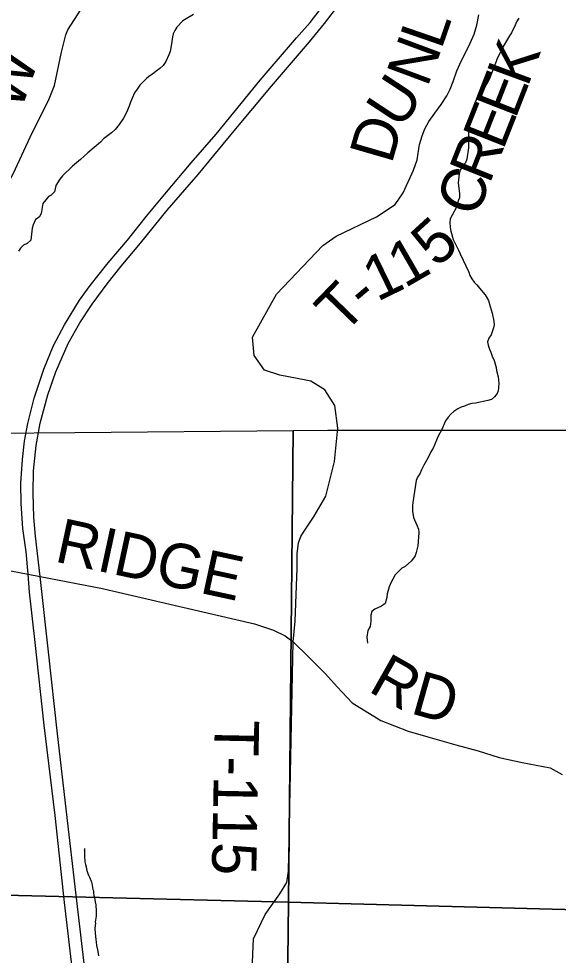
# Model space of a CAD drawing. Extents: x -14196 to 143, y -6096 to 28.
# Drawn here: x 60.879 to 61.569, y 20.751 to 21.949 of the extents above; entities that cross this region are included whole.
import ezdxf

# ---------------------------------------------------------------- set-up
doc = ezdxf.new("R2010")
doc.units = 0
for name, color, linetype in [('GM_X_Corporation', 7, 'Continuous'), ('GM_X_County_Road', 7, 'Continuous'), ('GM_X_County_Road_Text', 7, 'Continuous'), ('GM_X_Interstate_Route', 7, 'Continuous'), ('GM_X_Minor_River', 7, 'Continuous'), ('GM_X_Township_Road', 7, 'Continuous'), ('GM_X_Township_Road_Text', 7, 'Continuous')]:
    doc.layers.add(name, color=color, linetype=linetype)

msp = doc.modelspace()

# ---------------------------------------------------------------- linework, layer by layer
at = {"layer": 'GM_X_Corporation'}
for points in [[(60.9504, 21.4197), (61.23, 21.4222), (61.2237, 20.8189), (60.2211, 20.8437), (60.2221, 21.4121), (60.3073, 21.4131), (60.6364, 21.4168)], [(61.9287, 21.423), (62.2585, 21.4234), (62.2418, 20.9787), (62.2362, 20.7922), (61.2237, 20.8189), (61.23, 21.4222), (61.2736, 21.4223), (61.6017, 21.4227)], [(61.2237, 20.8189), (61.2122, 19.8148), (60.2036, 19.8271), (60.2211, 20.8437)], [(62.2362, 20.7922), (62.2333, 20.6565), (62.2314, 20.3211), (62.2297, 20.027), (62.2277, 19.7879), (61.2122, 19.8148), (61.2237, 20.8189)]]:
    msp.add_lwpolyline(points, close=True, dxfattribs=at)
at = {"layer": 'GM_X_County_Road'}
for points in [[(60.7945, 21.2541), (60.8181, 21.2522), (60.8595, 21.2442), (60.8908, 21.2382), (60.9059, 21.2353), (60.9859, 21.2201), (61.0005, 21.2167)], [(61.0005, 21.2167), (61.1804, 21.175), (61.2048, 21.1669), (61.2196, 21.1595), (61.2299, 21.1519), (61.2496, 21.1326), (61.2712, 21.1111), (61.2863, 21.0942), (61.3053, 21.074), (61.3422, 21.0512), (61.3768, 21.0377), (61.402, 21.0305), (61.4382, 21.0203), (61.4667, 21.0125), (61.4934, 21.0039), (61.5231, 20.9978), (61.5589, 20.9906), (61.5742, 20.9824)]]:
    msp.add_lwpolyline(points, dxfattribs=at)
at = {"layer": 'GM_X_Interstate_Route'}
for points in [[(60.9494, 20.7135), (60.9374, 20.8188), (60.9251, 20.9297), (60.9111, 21.0453), (60.8996, 21.1509), (60.8924, 21.2152), (60.8908, 21.2382), (60.8881, 21.267), (60.884, 21.2968), (60.8817, 21.3286), (60.8815, 21.3549), (60.8835, 21.3851), (60.8858, 21.4083), (60.8904, 21.4309), (60.8985, 21.4634), (60.9108, 21.5006), (60.9233, 21.5309), (60.9374, 21.5572), (60.9564, 21.5885), (60.9702, 21.6074), (60.9932, 21.6365), (61.0177, 21.6654), (61.0421, 21.6959), (61.0657, 21.7243), (61.0991, 21.7641), (61.1311, 21.801), (61.1541, 21.8288), (61.1876, 21.8699), (61.234, 21.9239), (61.2515, 21.9438), (61.2704, 21.9678)], [(60.9644, 20.7226), (60.9522, 20.828), (60.9397, 20.9346), (60.928, 21.0383), (60.917, 21.1353), (60.9059, 21.2353), (60.8999, 21.2871), (60.8979, 21.3107), (60.8969, 21.3419), (60.8977, 21.3704), (60.901, 21.4029), (60.9061, 21.4316), (60.916, 21.4676), (60.9259, 21.4972), (60.942, 21.5331), (60.9569, 21.5597), (60.9726, 21.5834), (60.992, 21.6097), (61.0098, 21.6323), (61.0344, 21.6614), (61.0686, 21.7036), (61.1081, 21.7494), (61.1545, 21.8051), (61.202, 21.8621), (61.2507, 21.9191), (61.27, 21.9423), (61.2882, 21.9665)]]:
    msp.add_lwpolyline(points, dxfattribs=at)
at = {"layer": 'GM_X_Minor_River'}
for points in [[(61.1024, 21.9539), (61.093, 21.9485), (61.0888, 21.9458), (61.0809, 21.9377), (61.0783, 21.9335), (61.0764, 21.9293), (61.0753, 21.9255), (61.0743, 21.9164), (61.0725, 21.9065), (61.0706, 21.9023), (61.0669, 21.8939), (61.0635, 21.8889)], [(61.5185, 21.9491), (61.5155, 21.9445), (61.514, 21.9403), (61.5092, 21.9304), (61.5066, 21.9265), (61.5043, 21.9223), (61.4987, 21.9132), (61.4961, 21.9074), (61.4909, 21.8975), (61.4898, 21.8937), (61.4879, 21.8895), (61.4805, 21.8708), (61.4749, 21.8601), (61.4719, 21.8563), (61.4696, 21.8521), (61.4659, 21.8475), (61.4629, 21.8421), (61.4614, 21.8376), (61.4592, 21.8338), (61.4559, 21.8219), (61.4548, 21.8166), (61.4542, 21.8044), (61.4544, 21.7835), (61.4522, 21.7691), (61.4504, 21.7641), (61.4466, 21.7599), (61.4436, 21.7549), (61.4422, 21.7504), (61.4411, 21.7386), (61.4428, 21.7245), (61.4425, 21.7196), (61.441, 21.7158), (61.4403, 21.712), (61.4388, 21.7078), (61.4332, 21.6975), (61.4309, 21.6925), (61.4302, 21.6883), (61.4307, 21.6815), (61.4315, 21.6769), (61.4346, 21.6663), (61.4416, 21.6527), (61.4436, 21.6478), (61.4545, 21.6243), (61.4561, 21.6201), (61.4584, 21.616), (61.4615, 21.6118), (61.4649, 21.6081), (61.4684, 21.6039), (61.4757, 21.5956), (61.48, 21.5881), (61.482, 21.5805), (61.4847, 21.5722), (61.4867, 21.5619), (61.4872, 21.557), (61.4864, 21.5532), (61.4831, 21.5444), (61.4801, 21.5402), (61.4786, 21.5356), (61.4794, 21.5311), (61.481, 21.5261), (61.483, 21.5224), (61.4845, 21.5171), (61.4869, 21.5114), (61.4896, 21.5027), (61.49, 21.4989), (61.4924, 21.4905), (61.4929, 21.4822), (61.4926, 21.4772), (61.4922, 21.473), (61.4911, 21.4692), (61.4877, 21.465), (61.4836, 21.4619), (61.479, 21.4604), (61.4631, 21.4572), (61.4585, 21.4568), (61.4536, 21.4552), (61.449, 21.4533), (61.4449, 21.4521), (61.4407, 21.4498), (61.4354, 21.4463)], [(61.0635, 21.8889), (61.0594, 21.8851), (61.0545, 21.8816), (61.0499, 21.8778), (61.0462, 21.8755), (61.0424, 21.8724), (61.0334, 21.8636), (61.0304, 21.8586), (61.0266, 21.8536), (61.0218, 21.8418), (61.0203, 21.838), (61.017, 21.8296), (61.0125, 21.8212), (61.0072, 21.8132), (61.002, 21.8067), (60.9974, 21.8028), (60.9872, 21.7951), (60.9831, 21.7905), (60.9669, 21.7771), (60.9578, 21.7686), (60.9476, 21.7602), (60.9345, 21.7475), (60.9311, 21.7433), (60.9262, 21.7353), (60.9244, 21.7273), (60.9202, 21.7231), (60.9165, 21.7211), (60.9135, 21.7169), (60.9093, 21.7123), (60.9075, 21.6994), (60.9046, 21.6948), (60.9, 21.6917), (60.897, 21.6852), (60.8956, 21.6807), (60.8942, 21.6654), (60.8893, 21.6612), (60.8848, 21.6589), (60.881, 21.6551), (60.8784, 21.6512)], [(61.4354, 21.4463), (61.4316, 21.4428), (61.4282, 21.439), (61.4249, 21.4344), (61.42, 21.4233), (61.4156, 21.4149), (61.4092, 21.3993), (61.4062, 21.3947), (61.4021, 21.3867), (61.3969, 21.3779), (61.3939, 21.3718), (61.3921, 21.3668), (61.3891, 21.3622), (61.3872, 21.358), (61.3829, 21.3299), (61.3826, 21.3257), (61.3827, 21.3189), (61.3839, 21.3109), (61.3882, 21.3011), (61.3901, 21.2958), (61.3906, 21.2916), (61.3892, 21.2748), (61.3874, 21.2661), (61.3859, 21.2619), (61.3814, 21.2554), (61.3731, 21.2481), (61.369, 21.2461), (61.3603, 21.2377), (61.3573, 21.232), (61.3551, 21.2282), (61.3528, 21.2224), (61.3503, 21.2133), (61.3499, 21.2087), (61.3474, 21.2011), (61.3428, 21.1973), (61.3345, 21.1938), (61.3303, 21.1907), (61.3292, 21.1861), (61.3293, 21.1781), (61.3282, 21.1713), (61.3253, 21.1663), (61.3242, 21.1579), (61.325, 21.1503)], [(60.9626, 20.8876), (60.9626, 20.885), (60.9626, 20.8857), (60.9627, 20.8823), (60.9627, 20.8796), (60.9627, 20.8758), (60.9632, 20.8732), (60.9632, 20.8705), (60.964, 20.8671), (60.9648, 20.8641), (60.9652, 20.8614), (60.966, 20.8584), (60.9672, 20.8557), (60.9679, 20.8535), (60.9691, 20.8508), (60.9699, 20.8489), (60.9707, 20.847), (60.9718, 20.8448), (60.9722, 20.8429), (60.9727, 20.841), (60.9731, 20.8379), (60.9735, 20.8353), (60.9743, 20.8334), (60.9743, 20.8311), (60.9747, 20.8277), (60.9755, 20.825), (60.9759, 20.8224), (60.9763, 20.8194), (60.9771, 20.8156), (60.9775, 20.8129), (60.9776, 20.8099), (60.9776, 20.8068), (60.9777, 20.8034), (60.9777, 20.8011), (60.9773, 20.7985), (60.977, 20.7962), (60.9766, 20.7939), (60.9767, 20.7916), (60.9763, 20.7897), (60.976, 20.7848), (60.9769, 20.7753), (60.9773, 20.7715), (60.9777, 20.7677), (60.9781, 20.7635), (60.9793, 20.7582), (60.9801, 20.7536), (60.9809, 20.7506)]]:
    msp.add_lwpolyline(points, dxfattribs=at)
at = {"layer": 'GM_X_Township_Road'}
for points in [[(60.6137, 21.5918), (60.6361, 21.5997), (60.6633, 21.6118), (60.688, 21.6197), (60.7126, 21.6288), (60.7516, 21.6391), (60.7744, 21.647), (60.8004, 21.6607), (60.82, 21.678), (60.8392, 21.6976), (60.8496, 21.7111), (60.872, 21.7512), (60.896, 21.8028), (60.9168, 21.8438), (60.9242, 21.8632), (60.9332, 21.9059), (60.939, 21.928), (60.9415, 21.9345), (60.9587, 21.9606)], [(61.235, 21.2511), (61.235, 21.2642), (61.2368, 21.2783), (61.2398, 21.2864), (61.243, 21.2921), (61.2566, 21.3126), (61.2715, 21.3383), (61.2827, 21.3825), (61.2871, 21.4251), (61.2833, 21.4539), (61.2705, 21.4739), (61.2525, 21.485), (61.246, 21.4865), (61.2128, 21.4929), (61.193, 21.4994), (61.1798, 21.5179), (61.1776, 21.5414), (61.2084, 21.5965), (61.2678, 21.6585), (61.2848, 21.6705), (61.3366, 21.6951), (61.3603, 21.711), (61.3708, 21.7259), (61.3837, 21.7549), (61.3886, 21.7681), (61.3917, 21.7878), (61.395, 21.7987), (61.3985, 21.8078), (61.4034, 21.8171), (61.411, 21.8279), (61.4194, 21.8388), (61.4263, 21.85), (61.4308, 21.8586), (61.4344, 21.8682), (61.4392, 21.8821), (61.443, 21.8905), (61.4564, 21.9174), (61.4615, 21.9289), (61.4651, 21.9404), (61.4675, 21.9535)], [(61.2299, 21.1519), (61.2323, 21.1782), (61.235, 21.246), (61.235, 21.2511)], [(61.1774, 20.7324), (61.1791, 20.772), (61.1942, 20.8032), (61.2129, 20.8298), (61.2216, 20.8444), (61.2238, 20.8587), (61.2241, 20.8786), (61.2299, 21.1519)]]:
    msp.add_lwpolyline(points, dxfattribs=at)

# ---------------------------------------------------------------- texts
at = {"layer": 'GM_X_County_Road_Text'}
for s, height, rotation, p in [('RIDGE', 0.05682, 347.812, (60.9231, 21.2549)), ('R', 0.0568, 330.4996, (61.3244, 21.0895)), ('D', 0.0568, 344.2191, (61.3785, 21.0609))]:
    msp.add_text(s, height=height, rotation=rotation, dxfattribs=at).set_placement(p)
at = {"layer": 'GM_X_Township_Road_Text'}
for s, height, rotation, p in [('L', 0.0568, 70.9609, (61.4194, 21.908)), ('N', 0.0568, 69.6141, (61.4015, 21.8598)), ('W', 0.0568, 70.4775, (60.8809, 21.8287)), ('K', 0.0568, 69.8254, (61.5299, 21.8599)), ('U', 0.0568, 56.6716, (61.3677, 21.8055)), ('E', 0.0568, 68.6569, (61.514, 21.8191)), ('E', 0.0568, 68.4205, (61.4983, 21.7794)), ('D', 0.0568, 73.8499, (61.3557, 21.7616)), ('R', 0.0568, 68.3841, (61.481, 21.736)), ('C', 0.0568, 68.3877, (61.4639, 21.6926)), ('5', 0.0568, 42.4996, (61.4138, 21.629)), ('1', 0.0568, 30.0337, (61.3726, 21.6035)), ('1', 0.0568, 26.0088, (61.3373, 21.5862)), ('T', 0.0568, 45.9758, (61.2942, 21.5436)), ('-', 0.0568, 40.1034, (61.3226, 21.5731)), ('T-115', 0.05682, 268.8762, (61.1296, 21.0524))]:
    msp.add_text(s, height=height, rotation=rotation, dxfattribs=at).set_placement(p)

doc.saveas('drawing.dxf')
